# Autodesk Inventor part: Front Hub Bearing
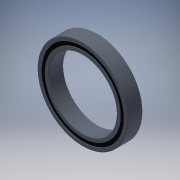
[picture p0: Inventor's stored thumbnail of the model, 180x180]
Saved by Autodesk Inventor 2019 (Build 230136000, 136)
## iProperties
Shininess: 50.0
Compacted: True
Length Units: 11272
Angle Units: 11279
Time Units: 11290
Mass Units: 11286
Length Display Precision: 4
Angle Display Precision: 2
Company: Autodesk
Created: 2000-05
Part Number: Front Hub Bearing
Project: Inventor Samples
User Status: IN PROGRESS
Document SubType Name: Modeling
Designer: Autodesk, Inc.
Density: 8.08 g/cm^3
Material: Stainless Steel
Mass: 3.10856 g
Surface Area: 5.95349 cm^2
Volume: 0.384722 cm^3
Appearance: Dark Grey
Density: 0.0
Volumn: 0.0
Area: 0.0
PropertySet Name: Model Information
Control State: 0
Master: False
Checked Out: False
Checked Out Date: 2018-05-30
Last Check In Date: 2018-05-30
Author: Autodesk, Inc.
Revision Number: A
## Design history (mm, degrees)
node "Extrusion1" dims "d5" = 3.175, "d6" = 0
  sketch "Sketch2"
    geometry: C1 r 7.144 at (10.478, 10.795); C2 r 9.525 at (10.478, 10.795); C3 r 8.712 at (10.478, 10.795); C4 r 7.957 at (10.478, 10.795)
    constraints: 4 centre point, 2 coincident, 1 concentric, 1 other
    dimensions: "d1" = 19.05 diameter of C2; "d2" = 0.8128 radial gap between concentric circles of C2 C3 (= d4); "d4" = 0.8128 radial gap between concentric circles of C1 C4; "d15" = 14.2875 diameter of C1
workplane "Work Plane1"
node "Fillet1" dims "d12" = 0.127
node "Chamfer1" dims "d13" = 0.127, "d14" = 0.127, "d18" = 45 deg
node "Extrusion2" dims "d16" = 2.921 (computed from d5), "d17" = 0
  sketch "Sketch4"
    geometry: C1 r 8.712 at (0, 0) reference; C2 r 7.957 at (0, 0) reference
body "Solid1"
other parameters: "d7" = -1.5875 (= -0.5 x d5)
